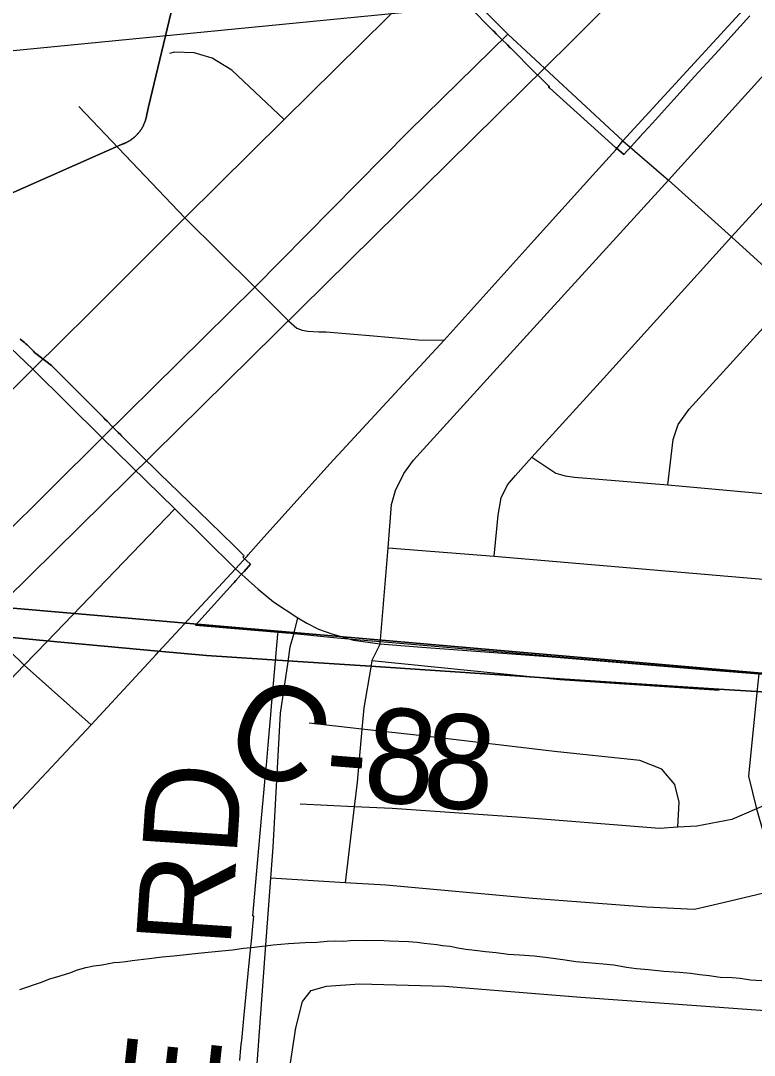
# Model space of a CAD drawing. Extents: x 0 to 34, y 0 to 22.
# Drawn here: x 8.123 to 8.563, y 15.871 to 16.492 of the extents above; entities that cross this region are included whole.
import ezdxf

# ---------------------------------------------------------------- set-up
doc = ezdxf.new("R2010")
doc.units = 0
for name, color, linetype in [('GM_X_City_Street', 7, 'Continuous'), ('GM_X_County_Road', 7, 'Continuous'), ('GM_X_County_Road_Text', 7, 'Continuous'), ('GM_X_Interchange_Ramps', 7, 'Continuous'), ('GM_X_Interstate_Route', 7, 'Continuous'), ('GM_X_Minor_River', 7, 'Continuous'), ('GM_X_Rail_Line', 7, 'Continuous'), ('GM_X_Section', 7, 'Continuous'), ('GM_X_Township_Road', 7, 'Continuous'), ('SH_Text', 7, 'Continuous')]:
    doc.layers.add(name, color=color, linetype=linetype)

msp = doc.modelspace()

# ---------------------------------------------------------------- linework, layer by layer
at = {"layer": 'GM_X_City_Street'}
for points in [[(8.33835, 16.11751), (8.34308, 16.17527), (8.34511, 16.20122), (8.34753, 16.20963), (8.35258, 16.2199), (8.35836, 16.22793), (8.43231, 16.30916), (8.5113, 16.39581), (8.63324, 16.531), (8.65014, 16.54856), (8.65854, 16.55406), (8.66536, 16.55621), (8.67301, 16.55696), (8.69608, 16.55462)], [(8.37339, 16.52405), (8.2806, 16.43228), (8.22113, 16.37332), (8.16411, 16.31618), (8.1299, 16.28249)], [(8.48387, 16.41957), (8.4149, 16.48356), (8.37409, 16.52474)], [(8.40675, 16.17024), (8.40902, 16.19489), (8.41089, 16.20514), (8.41471, 16.21307), (8.41955, 16.21866), (8.4293, 16.22966), (8.47222, 16.27683), (8.54895, 16.36183), (8.64838, 16.47069), (8.66506, 16.49008), (8.6728, 16.49809), (8.68296, 16.50341), (8.69321, 16.50704)], [(8.17149, 16.24118), (8.26314, 16.33162), (8.35557, 16.42534), (8.4149, 16.48356)], [(8.2806, 16.43228), (8.24924, 16.46196), (8.2376, 16.46908), (8.22666, 16.47238), (8.21488, 16.47264), (8.21183, 16.47195)], [(8.15758, 16.44007), (8.22113, 16.37332), (8.26314, 16.33162), (8.28326, 16.3114), (8.28833, 16.30711), (8.29155, 16.30579), (8.29496, 16.3053), (8.30149, 16.30492), (8.30588, 16.30487), (8.33435, 16.30243), (8.36134, 16.30009), (8.37663, 16.29994)], [(8.5108, 16.21298), (8.51401, 16.24025), (8.51702, 16.24927), (8.52358, 16.25843), (8.5866, 16.32773), (8.65495, 16.4032), (8.66931, 16.41796), (8.67683, 16.42425), (8.68475, 16.42835), (8.69542, 16.43273), (8.70266, 16.43409), (8.73599, 16.43611)], [(8.48387, 16.41957), (8.5113, 16.39581), (8.54895, 16.36183), (8.5866, 16.32773)], [(7.87223, 16.35799), (8.00507, 16.32655), (8.07321, 16.31066), (8.09296, 16.30636), (8.10543, 16.30265), (8.11211, 16.29953), (8.1299, 16.28249), (8.17149, 16.24118), (8.2151, 16.19863), (8.25155, 16.16262)], [(8.1299, 16.28249), (8.07211, 16.22469), (8.03712, 16.18997), (7.98088, 16.13342), (7.95899, 16.11066), (7.95041, 16.10203), (7.93352, 16.07348), (7.92426, 16.05521), (7.91817, 16.03901), (7.91292, 16.0197), (7.89919, 15.96229)], [(7.91292, 16.0197), (7.93431, 16.014), (7.9392, 16.01333), (7.94303, 16.01429), (7.94984, 16.01976), (7.99979, 16.06961), (8.05618, 16.12648), (8.0787, 16.14919), (8.17149, 16.24118)], [(8.4293, 16.22966), (8.44369, 16.21997), (8.44931, 16.21843), (8.45488, 16.21773), (8.5108, 16.21298), (8.57471, 16.20716), (8.63896, 16.20211), (8.69706, 16.1965), (8.70567, 16.19554), (8.71257, 16.1963)], [(7.94702, 15.91873), (7.97102, 15.94496), (7.99824, 15.97217), (8.04753, 16.02414), (8.12473, 16.10475), (8.13835, 16.1189), (8.2151, 16.19863)], [(8.03712, 16.18997), (8.0787, 16.14919), (8.10708, 16.12179), (8.12473, 16.10475), (8.16485, 16.06895)], [(8.34308, 16.17527), (8.40675, 16.17024), (8.57017, 16.15612), (8.75929, 16.14025), (8.7662, 16.14222), (8.7703, 16.14586)]]:
    msp.add_lwpolyline(points, dxfattribs=at)
at = {"layer": 'GM_X_County_Road'}
msp.add_line((8.25155, 16.16262), (8.25847, 16.17032), dxfattribs=at)
for points in [[(8.47972, 16.41398), (8.48387, 16.41957), (8.55596, 16.49806)], [(8.25847, 16.17032), (8.25916, 16.17109), (8.26693, 16.17974), (8.30818, 16.22567), (8.37663, 16.29994), (8.43059, 16.35982), (8.4677, 16.40082), (8.47972, 16.41398)], [(8.20396, 16.11127), (8.2053, 16.11273), (8.25155, 16.16262)], [(8.25155, 16.16262), (8.26518, 16.15041), (8.27423, 16.14287), (8.28892, 16.13325)], [(8.23991, 15.61928), (8.24297, 15.63215), (8.24426, 15.64337), (8.24865, 15.70168), (8.25183, 15.74595), (8.25923, 15.81021), (8.26439, 15.86282), (8.26911, 15.92883), (8.27269, 15.97705), (8.27406, 15.99556), (8.27853, 16.07595), (8.28303, 16.10686), (8.28432, 16.11573), (8.28656, 16.12333), (8.28892, 16.13325)], [(8.28892, 16.13325), (8.29427, 16.12999), (8.30129, 16.12648), (8.30928, 16.12354), (8.3222, 16.11978), (8.33835, 16.11751), (8.36064, 16.1159), (8.44151, 16.10976), (8.53488, 16.10201), (8.56547, 16.09969), (8.61558, 16.09502), (8.70644, 16.08725), (8.78702, 16.08014), (8.81015, 16.07861), (8.82142, 16.07772), (8.8264, 16.07724)], [(8.03059, 15.91949), (8.039, 15.92941), (8.06313, 15.95591), (8.08965, 15.98625), (8.12031, 16.02132), (8.16485, 16.06895), (8.20396, 16.11127)]]:
    msp.add_lwpolyline(points, dxfattribs=at)
at = {"layer": 'GM_X_Interchange_Ramps'}
for points in [[(8.21391, 16.50095), (8.19935, 16.4398), (8.19829, 16.43536), (8.19823, 16.43499), (8.19817, 16.43462), (8.1981, 16.43425), (8.19803, 16.43389), (8.19795, 16.43352), (8.19786, 16.43317), (8.19778, 16.43285), (8.19769, 16.43251), (8.19758, 16.43213), (8.19746, 16.43174), (8.19733, 16.43136), (8.19719, 16.43097), (8.19706, 16.4306), (8.19691, 16.43021), (8.19676, 16.42985), (8.19658, 16.42945), (8.1964, 16.42905), (8.19622, 16.42867), (8.19604, 16.42832), (8.19585, 16.42795), (8.19566, 16.42761), (8.19545, 16.42724), (8.19525, 16.42691), (8.19503, 16.42655), (8.19478, 16.42617), (8.19454, 16.42582), (8.19431, 16.42549), (8.19407, 16.42516), (8.19382, 16.42484), (8.19357, 16.42452), (8.19331, 16.42421), (8.19305, 16.4239), (8.19278, 16.42359), (8.19251, 16.42329), (8.19223, 16.423), (8.19194, 16.42271), (8.19165, 16.42243), (8.19136, 16.42215), (8.19106, 16.42188), (8.19075, 16.42161), (8.19044, 16.42135), (8.19013, 16.42109), (8.18981, 16.42084), (8.18949, 16.4206), (8.18919, 16.42038), (8.18888, 16.42016), (8.18855, 16.41993), (8.18821, 16.41971), (8.18786, 16.4195), (8.18752, 16.41929), (8.18717, 16.41909), (8.18681, 16.41889), (8.18645, 16.4187), (8.18609, 16.41852), (8.18576, 16.41835), (8.18542, 16.4182), (8.18513, 16.41807), (8.18486, 16.41795), (8.18456, 16.41783), (8.1843, 16.41772), (8.18405, 16.41763), (8.18374, 16.41751), (8.18345, 16.41741), (8.18316, 16.41731), (8.11142, 16.38553)], [(8.11142, 16.38553), (8.18316, 16.41731), (8.18345, 16.41741), (8.18374, 16.41751), (8.18405, 16.41763), (8.1843, 16.41772), (8.18456, 16.41783), (8.18486, 16.41795), (8.18513, 16.41807), (8.18542, 16.4182), (8.18576, 16.41835), (8.18609, 16.41852), (8.18645, 16.4187), (8.18681, 16.41889), (8.18717, 16.41909), (8.18752, 16.41929), (8.18786, 16.4195), (8.18821, 16.41971), (8.18855, 16.41993), (8.18888, 16.42016), (8.18919, 16.42038), (8.18949, 16.4206), (8.18981, 16.42084), (8.19013, 16.42109), (8.19044, 16.42135), (8.19075, 16.42161), (8.19106, 16.42188), (8.19136, 16.42215), (8.19165, 16.42243), (8.19194, 16.42271), (8.19223, 16.423), (8.19251, 16.42329), (8.19278, 16.42359), (8.19305, 16.4239), (8.19331, 16.42421), (8.19357, 16.42452), (8.19382, 16.42484), (8.19407, 16.42516), (8.19431, 16.42549), (8.19454, 16.42582), (8.19478, 16.42617), (8.19503, 16.42655), (8.19525, 16.42691), (8.19545, 16.42724), (8.19566, 16.42761), (8.19585, 16.42795), (8.19604, 16.42832), (8.19622, 16.42867), (8.1964, 16.42905), (8.19658, 16.42945), (8.19676, 16.42985), (8.19691, 16.43021), (8.19706, 16.4306), (8.19719, 16.43097), (8.19733, 16.43136), (8.19746, 16.43174), (8.19758, 16.43213), (8.19769, 16.43251), (8.19778, 16.43285), (8.19786, 16.43317), (8.19795, 16.43352), (8.19803, 16.43389), (8.1981, 16.43425), (8.19817, 16.43462), (8.19822, 16.43494), (8.19823, 16.43499), (8.19829, 16.43536), (8.19935, 16.4398), (8.21391, 16.50095)], [(8.55999, 16.49443), (8.55232, 16.48598), (8.54337, 16.47611), (8.53442, 16.46625), (8.52675, 16.4578), (8.51831, 16.4485), (8.51064, 16.44005), (8.50157, 16.43005), (8.4939, 16.4216), (8.49383, 16.42152), (8.49376, 16.42145), (8.4937, 16.42138), (8.49363, 16.4213), (8.49357, 16.42123), (8.4935, 16.42116), (8.49344, 16.42109), (8.49245, 16.42), (8.48899, 16.41622), (8.48443, 16.41121), (8.4844, 16.41118), (8.48439, 16.41119), (8.47991, 16.41522), (8.47975, 16.41536), (8.4751, 16.41955), (8.43977, 16.4513), (8.43933, 16.45169), (8.43944, 16.45179), (8.43945, 16.4518), (8.43964, 16.452), (8.43973, 16.45209), (8.43963, 16.45219), (8.43931, 16.4525), (8.43531, 16.4564), (8.4353, 16.45641), (8.43089, 16.46071), (8.41664, 16.47502), (8.41663, 16.47503), (8.41657, 16.47509), (8.41656, 16.4751), (8.4165, 16.47516), (8.41649, 16.47517), (8.41643, 16.47523), (8.41642, 16.47524), (8.41636, 16.4753), (8.41635, 16.47531), (8.41629, 16.47537), (8.41628, 16.47538), (8.41622, 16.47544), (8.41621, 16.47545), (8.41615, 16.47551), (8.41615, 16.47551), (8.41464, 16.47703), (8.4111, 16.48058), (8.40795, 16.48374), (8.40643, 16.48527), (8.40642, 16.48528), (8.40636, 16.48534), (8.40636, 16.48534), (8.4063, 16.4854), (8.40629, 16.48541), (8.40623, 16.48547), (8.40622, 16.48548), (8.40616, 16.48554), (8.40615, 16.48555), (8.40609, 16.48561), (8.40608, 16.48562), (8.40602, 16.48568), (8.40601, 16.48569), (8.40595, 16.48575), (8.40594, 16.48576), (8.39125, 16.50052)], [(8.39125, 16.50052), (8.40594, 16.48576), (8.40595, 16.48575), (8.40601, 16.48569), (8.40602, 16.48568), (8.40608, 16.48562), (8.40609, 16.48561), (8.40615, 16.48555), (8.40616, 16.48554), (8.40622, 16.48548), (8.40623, 16.48547), (8.40629, 16.48541), (8.4063, 16.4854), (8.40636, 16.48534), (8.40636, 16.48534), (8.40642, 16.48528), (8.40643, 16.48527), (8.40795, 16.48374), (8.4111, 16.48058), (8.41464, 16.47703), (8.41615, 16.47551), (8.41615, 16.47551), (8.41621, 16.47545), (8.41622, 16.47544), (8.41628, 16.47538), (8.41629, 16.47537), (8.41635, 16.47531), (8.41636, 16.4753), (8.41642, 16.47524), (8.41643, 16.47523), (8.41649, 16.47517), (8.4165, 16.47516), (8.41656, 16.4751), (8.41657, 16.47509), (8.41663, 16.47503), (8.41664, 16.47502), (8.43088, 16.46072), (8.43089, 16.46071), (8.4353, 16.45641), (8.43531, 16.4564), (8.43931, 16.4525), (8.43963, 16.45219), (8.43973, 16.45209), (8.43964, 16.452), (8.43945, 16.4518), (8.43944, 16.45179), (8.43933, 16.45169), (8.43977, 16.4513), (8.4751, 16.41955), (8.47511, 16.41954), (8.47975, 16.41536), (8.47991, 16.41522), (8.48439, 16.41119), (8.4844, 16.41118), (8.48443, 16.41121), (8.48899, 16.41622), (8.49245, 16.42), (8.49344, 16.42109), (8.4935, 16.42116), (8.49357, 16.42123), (8.49363, 16.4213), (8.4937, 16.42138), (8.49376, 16.42145), (8.49383, 16.42152), (8.4939, 16.4216), (8.50157, 16.43005), (8.51064, 16.44005), (8.51831, 16.4485), (8.52675, 16.4578), (8.53442, 16.46625), (8.54337, 16.47611), (8.55232, 16.48598), (8.55999, 16.49443)], [(8.12238, 16.30041), (8.12321, 16.29977), (8.12322, 16.29977), (8.12404, 16.29911), (8.12405, 16.2991), (8.12485, 16.29843), (8.12486, 16.29842), (8.12503, 16.29828), (8.12566, 16.29774), (8.12567, 16.29773), (8.12645, 16.29703), (8.12646, 16.29703), (8.12723, 16.29632), (8.12724, 16.29631), (8.128, 16.29558), (8.12801, 16.29557), (8.12875, 16.29484), (8.12876, 16.29483), (8.1295, 16.29408), (8.1295, 16.29407), (8.12951, 16.29406), (8.13022, 16.2933), (8.13023, 16.29329), (8.13025, 16.29328), (8.13094, 16.29252), (8.13095, 16.29251), (8.13109, 16.29235), (8.1311, 16.29234), (8.13111, 16.29233), (8.1326, 16.29119), (8.13612, 16.28848), (8.13615, 16.28846), (8.13773, 16.28724), (8.14102, 16.28471), (8.14103, 16.2847), (8.15774, 16.26798), (8.15775, 16.26797), (8.16744, 16.25823), (8.16745, 16.25822), (8.17244, 16.25321), (8.17245, 16.25321), (8.17251, 16.25314), (8.17252, 16.25314), (8.17258, 16.25307), (8.17259, 16.25307), (8.17265, 16.253), (8.17266, 16.25299), (8.17272, 16.25293), (8.17273, 16.25293), (8.17279, 16.25287), (8.1728, 16.25286), (8.17286, 16.2528), (8.17287, 16.25279), (8.17292, 16.25273), (8.17293, 16.25272), (8.17445, 16.25119), (8.1777, 16.24793), (8.17775, 16.24788), (8.18114, 16.24448), (8.18265, 16.24297), (8.18266, 16.24296), (8.18272, 16.2429), (8.18272, 16.24289), (8.18278, 16.24283), (8.18279, 16.24282), (8.18285, 16.24276), (8.18286, 16.24275), (8.18292, 16.24269), (8.18293, 16.24268), (8.18299, 16.24262), (8.183, 16.24261), (8.18306, 16.24255), (8.18307, 16.24254), (8.18314, 16.24247), (8.19783, 16.22772), (8.19784, 16.22771), (8.20191, 16.22376), (8.20192, 16.22375), (8.20599, 16.2198), (8.22365, 16.20265), (8.22366, 16.20264), (8.23588, 16.19077), (8.23589, 16.19076), (8.25063, 16.17645), (8.25064, 16.17644), (8.25675, 16.17051), (8.25596, 16.16964), (8.26057, 16.16539), (8.2566, 16.16102), (8.25595, 16.16031), (8.25555, 16.15987), (8.25547, 16.15978), (8.25479, 16.15903), (8.2517, 16.15563), (8.25062, 16.15444), (8.25002, 16.15378), (8.22745, 16.12882), (8.27705, 16.12466), (8.27927, 16.12447), (8.28166, 16.12427), (8.28271, 16.12419), (8.31258, 16.12122), (8.33334, 16.11944), (8.33365, 16.11941), (8.81108, 16.07867)], [(8.2541, 15.86761), (8.25477, 15.87514), (8.25514, 15.87883), (8.2552, 15.87948), (8.25672, 15.89486), (8.25978, 15.926), (8.26093, 15.93759), (8.26108, 15.93916), (8.26197, 15.94819), (8.26256, 15.95427), (8.26193, 15.95416), (8.26477, 15.98598), (8.26739, 16.01521), (8.2699, 16.04331), (8.27003, 16.04479), (8.2711, 16.05674), (8.27294, 16.07732), (8.27298, 16.07773), (8.27694, 16.12344), (8.27705, 16.12466), (8.22745, 16.12882), (8.25002, 16.15378), (8.25062, 16.15444), (8.2517, 16.15563), (8.25479, 16.15903), (8.25547, 16.15978), (8.25555, 16.15987), (8.25595, 16.16031), (8.2566, 16.16102), (8.26057, 16.16539), (8.25596, 16.16964), (8.25675, 16.17051), (8.25064, 16.17644), (8.25063, 16.17645), (8.23589, 16.19076), (8.23588, 16.19077), (8.22366, 16.20264), (8.22365, 16.20265), (8.206, 16.21979), (8.20599, 16.2198), (8.20191, 16.22376), (8.19784, 16.22771), (8.19783, 16.22772), (8.18314, 16.24247), (8.18313, 16.24248), (8.18307, 16.24254), (8.18306, 16.24255), (8.183, 16.24261), (8.18299, 16.24262), (8.18293, 16.24268), (8.18292, 16.24269), (8.18286, 16.24275), (8.18285, 16.24276), (8.18279, 16.24282), (8.18278, 16.24283), (8.18272, 16.24289), (8.18272, 16.2429), (8.18266, 16.24296), (8.18265, 16.24297), (8.18114, 16.24448), (8.17775, 16.24788), (8.1777, 16.24793), (8.17445, 16.25119), (8.17293, 16.25272), (8.17292, 16.25273), (8.17287, 16.25279), (8.17286, 16.2528), (8.1728, 16.25286), (8.17279, 16.25287), (8.17273, 16.25293), (8.17272, 16.25293), (8.17266, 16.25299), (8.17259, 16.25307), (8.17258, 16.25307), (8.17252, 16.25314), (8.17251, 16.25314), (8.17245, 16.25321), (8.17244, 16.25321), (8.16745, 16.25822), (8.16744, 16.25823), (8.15775, 16.26797), (8.15774, 16.26798), (8.14103, 16.2847), (8.14102, 16.28471), (8.13773, 16.28724), (8.13615, 16.28846), (8.13612, 16.28848), (8.1326, 16.29119), (8.13111, 16.29233), (8.13109, 16.29235), (8.13094, 16.29252), (8.13025, 16.29328), (8.13023, 16.29329), (8.13022, 16.2933), (8.12951, 16.29406), (8.1295, 16.29407), (8.1295, 16.29408), (8.12876, 16.29483), (8.12875, 16.29484), (8.12801, 16.29557), (8.128, 16.29558), (8.12724, 16.29631), (8.12723, 16.29632), (8.12646, 16.29703), (8.12645, 16.29703), (8.12567, 16.29773), (8.12566, 16.29774), (8.12503, 16.29828), (8.12486, 16.29842), (8.12485, 16.29843), (8.12405, 16.2991), (8.12404, 16.29911), (8.12322, 16.29977), (8.12321, 16.29977), (8.12238, 16.30041)]]:
    msp.add_lwpolyline(points, dxfattribs=at)
at = {"layer": 'GM_X_Interstate_Route'}
for points in [[(8.72803, 15.03589), (8.74501, 15.2262), (8.76372, 15.43606), (8.77169, 15.52546), (8.78175, 15.63825), (8.78282, 15.65018), (8.78628, 15.68902), (8.80068, 15.85393), (8.81331, 15.99866), (8.81973, 16.07216), (8.79264, 16.07393), (8.78619, 16.07435), (8.57525, 16.0882), (8.56409, 16.08893), (8.5415, 16.09042), (8.4459, 16.09669), (8.33242, 16.10414), (8.28279, 16.10739), (8.23418, 16.11058), (8.20507, 16.11326), (8.13812, 16.11944), (8.10685, 16.12232)], [(8.10685, 16.12232), (8.13812, 16.11944), (8.20507, 16.11326), (8.23418, 16.11058), (8.28279, 16.10739), (8.33242, 16.10414), (8.4459, 16.09669), (8.5415, 16.09042), (8.56409, 16.08893), (8.57525, 16.0882), (8.78619, 16.07435), (8.79264, 16.07393), (8.81973, 16.07216), (8.81331, 15.99866), (8.80068, 15.85393), (8.78628, 15.68902), (8.78282, 15.65018), (8.78175, 15.63825), (8.77169, 15.52546), (8.76372, 15.43606), (8.74501, 15.2262), (8.72803, 15.03589)]]:
    msp.add_lwpolyline(points, dxfattribs=at)
at = {"layer": 'GM_X_Minor_River'}
msp.add_lwpolyline([(8.12214, 15.9102), (8.13442, 15.91446), (8.14017, 15.9166), (8.1463, 15.91835), (8.15205, 15.92011), (8.15666, 15.9219), (8.16164, 15.9233), (8.1666, 15.92432), (8.17156, 15.92495), (8.17844, 15.92631), (8.18187, 15.9266), (8.18568, 15.92689), (8.1895, 15.92755), (8.1998, 15.92882), (8.20743, 15.92977), (8.21429, 15.93036), (8.22001, 15.93098), (8.22535, 15.93161), (8.23107, 15.93223), (8.24327, 15.93345), (8.24975, 15.93405), (8.25624, 15.93503), (8.26272, 15.93563), (8.27416, 15.93687), (8.28331, 15.93778), (8.29321, 15.9383), (8.30044, 15.9385), (8.30654, 15.93911), (8.31149, 15.93936), (8.31643, 15.93924), (8.32024, 15.93953), (8.32443, 15.9398), (8.33013, 15.93966), (8.33736, 15.93986), (8.34382, 15.93932), (8.35522, 15.93904), (8.36053, 15.93852), (8.3647, 15.93804), (8.37228, 15.93709), (8.3757, 15.93662), (8.38025, 15.93613), (8.38479, 15.93526), (8.38971, 15.93437), (8.39502, 15.93386), (8.40146, 15.93294), (8.40792, 15.9324), (8.41512, 15.93146), (8.42195, 15.93091), (8.43068, 15.93031), (8.43903, 15.92934), (8.44926, 15.92795), (8.4557, 15.92702), (8.46291, 15.92646), (8.47202, 15.92548), (8.47847, 15.92494), (8.48604, 15.9236), (8.4921, 15.92269), (8.49932, 15.92213), (8.50842, 15.92115), (8.51791, 15.92053), (8.52437, 15.91999), (8.53005, 15.91909), (8.53574, 15.91856), (8.54218, 15.91764), (8.5494, 15.91746), (8.55433, 15.91696), (8.5604, 15.91605), (8.56723, 15.9155)], dxfattribs=at)
at = {"layer": 'GM_X_Rail_Line'}
msp.add_lwpolyline([(7.56811, 15.60595), (8.45273, 16.47869), (8.56606, 16.59234), (8.60997, 16.64414), (8.67413, 16.73275), (8.72397, 16.82286), (8.76125, 16.92452), (8.81965, 17.10025), (8.84855, 17.20132)], dxfattribs=at)
at = {"layer": 'GM_X_Section'}
for points in [[(7.88532, 17.20474), (8.90934, 17.12155), (8.83221, 16.07695), (7.80451, 16.16627)], [(7.80451, 16.16627), (8.83221, 16.07695), (8.73592, 15.03992), (7.71554, 15.1965)]]:
    msp.add_lwpolyline(points, close=True, dxfattribs=at)
at = {"layer": 'GM_X_Township_Road'}
for points in [[(8.33835, 16.11751), (8.33334, 16.10764), (8.33265, 16.10361), (8.32849, 16.0792), (8.32737, 16.06641), (8.32455, 16.0345), (8.32276, 16.0198), (8.31722, 15.97423)], [(8.33334, 16.10764), (8.44614, 16.09616), (8.54173, 16.08989)], [(8.56547, 16.09969), (8.56432, 16.0884), (8.55921, 16.0381), (8.56414, 16.0186), (8.57248, 15.98939), (8.58027, 15.97119), (8.58427, 15.95103), (8.58427, 15.93774), (8.57995, 15.89666), (8.57546, 15.84063)], [(8.51695, 16.00752), (8.51769, 16.02264), (8.51508, 16.03316), (8.50718, 16.04237), (8.49406, 16.04762), (8.44281, 16.0529), (8.36529, 16.06212), (8.32737, 16.06641), (8.29565, 16.07001)], [(8.78215, 16.02479), (8.71216, 16.03578), (8.64646, 16.04105), (8.62282, 16.03973), (8.60311, 16.03578), (8.57945, 16.02527), (8.56414, 16.0186), (8.54924, 16.01212), (8.5282, 16.00818), (8.51695, 16.00752), (8.50587, 16.00687), (8.42309, 16.01346), (8.34557, 16.01871), (8.32276, 16.0198), (8.29038, 16.02135)], [(8.76865, 15.98304), (8.72136, 15.98843), (8.66223, 15.99239), (8.64909, 15.9924), (8.63463, 15.98843), (8.62721, 15.98618), (8.60441, 15.97924), (8.58027, 15.97119), (8.57681, 15.97004), (8.54398, 15.96216), (8.52689, 15.95821), (8.49799, 15.95952), (8.42966, 15.9648), (8.34163, 15.97269), (8.31722, 15.97423), (8.27269, 15.97705)], [(8.28382, 15.86222), (8.28776, 15.88723), (8.2917, 15.903), (8.29695, 15.90957), (8.30615, 15.91221), (8.32587, 15.91351), (8.3771, 15.91221), (8.45858, 15.90562), (8.53083, 15.90035), (8.57995, 15.89666), (8.58338, 15.8964), (8.63332, 15.89376)]]:
    msp.add_lwpolyline(points, dxfattribs=at)
at = {"layer": 'SH_Text'}
msp.add_lwpolyline([(9.61689, 16.98057), (3.73843, 16.04511), (9.61689, 16.62061)], close=True, dxfattribs=at)

# ---------------------------------------------------------------- texts
at = {"layer": 'GM_X_County_Road_Text'}
for s, height, rotation, p in [('C', 0.05682, 336.71121, (8.24136, 16.04919)), ('8', 0.05682, 354.17704, (8.32678, 16.02406)), ('8', 0.05682, 355.12902, (8.36263, 16.02042)), ('-', 0.05682, 355.47463, (8.30386, 16.02588)), ('RD', 0.056818, 86.15448, (8.24841, 15.93471)), ('LAMME', 0.056818, 83.75101, (8.21435, 15.61084))]:
    msp.add_text(s, height=height, rotation=rotation, dxfattribs=at).set_placement(p)

doc.saveas('drawing.dxf')
